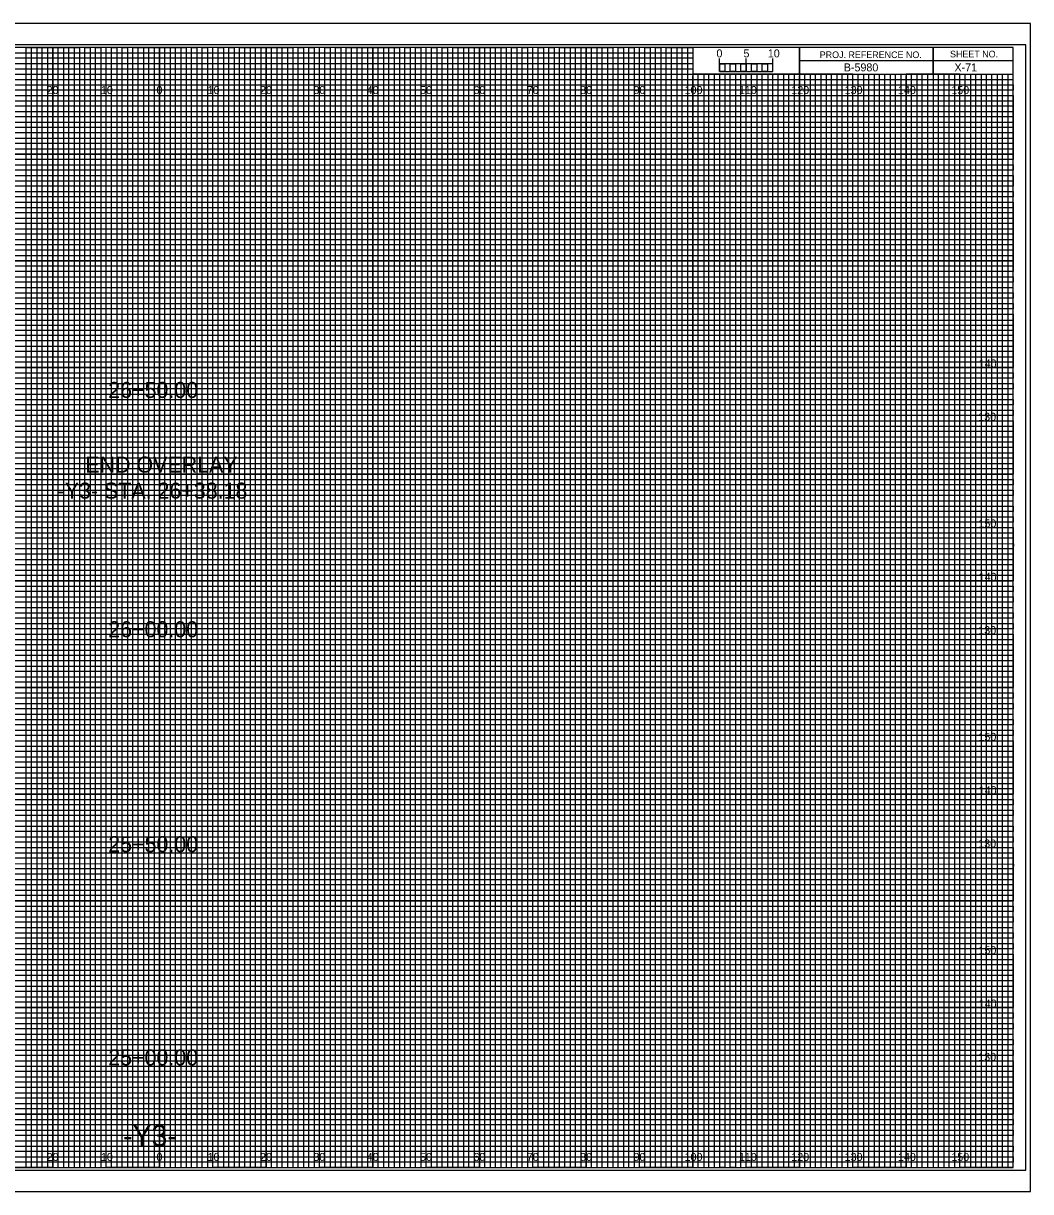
# Model space of a CAD drawing. Extents: x -13 to 323, y -5 to 434.
# Drawn here: x 134.5 to 323.3, y 215.5 to 434.5 of the extents above; entities that cross this region are included whole.
import ezdxf

# ---------------------------------------------------------------- set-up
doc = ezdxf.new("R2010")
doc.units = 0
for name, color, linetype in [('Exist Cross Section Cell', 7, 'Continuous'), ('Exist XS Center Line Elevation Label', 7, 'Continuous'), ('Exist XS Ground Line', 7, 'Continuous'), ('Prop CMT Pvmt Course 1', 7, 'Continuous'), ('Prop CMT Pvmt Course 2', 7, 'Continuous'), ('Prop CMT Pvmt Course 3', 7, 'Continuous'), ('Prop CMT Pvmt Surface', 7, 'Continuous'), ('Prop CMT Pvmt Surface Shoulder', 7, 'Continuous'), ('Prop CMT Shld Paved Course 1', 7, 'Continuous'), ('Prop CMT Shld Paved Course 2', 7, 'Continuous'), ('Prop CMT Shld Paved Course 3', 7, 'Continuous'), ('Prop CMT Slope Grass', 7, 'Continuous'), ('Prop CMT Subgrade Earthwork', 7, 'Continuous'), ('Prop SS Cut Text', 7, 'Continuous'), ('Prop SS Fill Line', 7, 'Continuous'), ('Prop SS Transition Line', 7, 'Continuous'), ('Prop XS Side Slope Text', 7, 'Continuous')]:
    doc.layers.add(name, color=color, linetype=linetype)

msp = doc.modelspace()

# ---------------------------------------------------------------- linework, layer by layer
at = {"layer": 'Exist XS Center Line Elevation Label'}
for points in [[(125, 220), (135, 220), (135, 430), (145, 430), (145, 220), (155, 220), (155, 430), (165, 430), (165, 220), (175, 220), (175, 430), (185, 430), (185, 220), (195, 220), (195, 430), (205, 430), (205, 220), (215, 220), (215, 430), (225, 430), (225, 220), (235, 220), (235, 430), (245, 430), (245, 220), (255, 220), (255, 430), (259.93, 430), (260, 430), (260, 425), (264.99, 425), (264.99, 220), (275, 220), (275, 425), (285, 425), (285, 220), (295, 220), (295, 425), (305, 425), (305, 220), (315, 220), (315, 425)], [(0, 425), (275, 425)], [(0, 405), (320, 405), (320, 415), (0, 415)], [(0, 385), (320, 385), (320, 395), (0, 395)], [(0, 365), (320, 365), (320, 375), (0, 375)], [(0, 345), (320, 345), (320, 355), (0, 355)], [(0, 325), (320, 325), (320, 335), (0, 335)], [(0, 305), (320, 305), (320, 315), (0, 315)], [(0, 285), (320, 285), (320, 295), (0, 295)], [(0, 265), (320, 265), (320, 275), (0, 275)], [(0, 245), (320, 245), (320, 255), (0, 255)], [(0, 225), (320, 225), (320, 235), (0, 235)]]:
    msp.add_lwpolyline(points, dxfattribs=at)
at = {"layer": 'Exist XS Ground Line'}
for p, q in [((150, 430), (140, 430)), ((140, 430), (140, 220)), ((150, 220), (150, 430)), ((170, 430), (160, 430)), ((160, 430), (160, 220)), ((170, 220), (170, 430)), ((190, 430), (180, 430)), ((180, 430), (180, 220)), ((190, 220), (190, 430)), ((210, 430), (200, 430)), ((200, 430), (200, 220)), ((210, 220), (210, 430)), ((230, 430), (220, 430)), ((220, 430), (220, 220)), ((230, 220), (230, 430)), ((250, 430), (240, 430)), ((240, 430), (240, 220)), ((250, 220), (250, 430)), ((260, 430), (260, 220)), ((270, 220), (270, 425)), ((290, 425), (280, 425)), ((280, 425), (280, 220)), ((290, 220), (290, 425)), ((310, 425), (300, 425)), ((300, 425), (300, 220)), ((310, 220), (310, 425)), ((140, 220), (130, 220)), ((160, 220), (150, 220)), ((180, 220), (170, 220)), ((200, 220), (190, 220)), ((220, 220), (210, 220)), ((240, 220), (230, 220)), ((260, 220), (250, 220)), ((280, 220), (270, 220)), ((300, 220), (290, 220)), ((320, 220), (310, 220)), ((320, 220), (320, 220))]:
    msp.add_line(p, q, dxfattribs=at)
for points in [[(0, 420), (320, 420), (320, 410), (0, 410)], [(0, 400), (320, 400), (320, 390), (0, 390)], [(0, 380), (320, 380), (320, 370), (0, 370)], [(0, 360), (320, 360), (320, 350), (0, 350)], [(0, 340), (320, 340), (320, 330), (0, 330)], [(0, 320), (320, 320), (320, 310), (0, 310)], [(0, 300), (320, 300), (320, 290), (0, 290)], [(0, 280), (320, 280), (320, 270), (0, 270)], [(0, 260), (320, 260), (320, 250), (0, 250)], [(0, 240), (320, 240), (320, 230), (0, 230)]]:
    msp.add_lwpolyline(points, dxfattribs=at)
at = {"layer": 'Prop CMT Pvmt Course 1'}
for p, q in [((265, 425.49), (265, 427.9)), ((265, 426.9), (265, 427.9)), ((270, 425.49), (270, 427.9)), ((275, 425.49), (275, 427.9)), ((275, 426.9), (275, 427.9))]:
    msp.add_line(p, q, dxfattribs=at)
for points in [[(275, 426.9), (265, 426.9), (265, 425.49), (275, 425.49)], [(265, 426.9), (266, 426.9), (266, 425.49), (265, 425.49)], [(267, 426.9), (268, 426.9), (268, 425.49), (267, 425.49)], [(269, 426.9), (270, 426.9), (270, 425.49), (269, 425.49)], [(271, 426.9), (272, 426.9), (272, 425.49), (271, 425.49)], [(273, 426.9), (274, 426.9), (274, 425.49), (273, 425.49)]]:
    msp.add_lwpolyline(points, close=True, dxfattribs=at)
at = {"layer": 'Prop CMT Pvmt Course 2'}
for p, q in [((0, 429), (260, 429)), ((260, 427.98), (0, 427.98)), ((260, 429), (260, 427.98)), ((0, 427), (260, 427)), ((260, 425.89), (0, 425.89)), ((260, 427), (260, 425.89)), ((0, 424), (320, 424))]:
    msp.add_line(p, q, dxfattribs=at)
for points in [[(0, 423), (270, 423), (320, 423), (320, 422), (0, 422)], [(0, 421), (320, 421), (320, 419), (0, 419)], [(0, 418), (320, 418), (320, 417), (0, 416.98)], [(0, 416), (320, 416), (320, 414), (0, 414)], [(0, 413), (320, 413), (320, 412), (0, 412)], [(0, 411), (320, 411), (320, 409), (0, 409)], [(0, 408), (320, 408), (320, 407), (0, 407)], [(0, 406), (320, 406), (320, 404), (0, 404)], [(0, 403), (320, 403), (320, 402), (0, 402)], [(0, 401), (320, 401), (320, 399), (0, 399)], [(0, 398), (320, 398), (320, 397), (0, 397)], [(0, 396), (320, 396), (320, 393.95), (320, 393), (320, 392), (0, 392)], [(0, 394), (320, 394), (320, 393), (0, 393)], [(0, 391), (320, 391), (320, 389), (0, 389.03)], [(0, 389.03), (320, 389), (320, 388), (0, 388)], [(0, 387), (320, 387), (320, 386), (0, 386)], [(0, 384), (320, 384), (320, 383), (0, 383)], [(0, 382), (320, 382), (320, 381), (0, 381)], [(-0.07, 378.89), (320, 378.89), (320, 377.88), (-0.07, 377.88)], [(0, 377), (320, 377), (320, 376), (0, 376)], [(0, 374), (320, 374), (320, 373), (0, 373)], [(0, 372), (320, 372), (320, 371), (0, 371)], [(0, 369), (320, 369), (320, 368), (0, 368)], [(0, 367), (320, 367), (320, 366), (0, 366)], [(0, 364), (320, 364), (320, 363), (0, 363)], [(0, 362), (320, 362), (320, 361), (0, 361)], [(0, 359), (320, 359), (319.99, 357.98), (0, 358)], [(0, 357), (320, 357), (320, 356), (0, 356)], [(0, 354), (320, 354), (320, 353), (0, 353)], [(0, 352), (320, 352), (320, 351), (0, 351)], [(0, 349), (320, 349), (320, 348), (0, 348)], [(0, 347), (320, 347), (320, 346), (0, 346)], [(0, 344), (320, 344), (320, 343), (0, 343)], [(0, 342), (320, 342), (320, 341), (0, 341)], [(0, 339), (320, 339), (320, 338), (0, 338)], [(0, 336.99), (320.07, 336.91), (320, 336), (0, 336)], [(0, 334), (320, 334), (320, 333), (0, 333)], [(0, 332), (320, 332), (320, 331), (0, 331)], [(0, 329), (320, 329), (320, 328), (0, 328)], [(0, 327), (320, 327), (320, 326), (0, 326)], [(0, 324), (320, 324), (320, 323), (0, 323)], [(0, 322), (320, 322), (320, 321), (0, 321)], [(0, 319), (320, 319), (320, 318), (0, 318)], [(0, 317), (320, 317), (320, 316), (0, 316)], [(0, 314), (320, 314), (320, 313), (0, 313)], [(0, 312), (320, 312), (320, 311), (0, 311)], [(0, 309), (320, 309), (320, 308), (0, 308)], [(0, 307), (320, 307), (320, 306), (0, 306)], [(0, 304), (320, 304), (320, 303), (0, 303)], [(0, 302), (320, 302), (320, 301), (0, 301)], [(0, 299), (320, 299), (319.99, 297.98), (0, 298)], [(0, 297), (320, 297), (320, 296), (0, 296)], [(0, 294), (320, 294), (320, 293), (0, 293)], [(0, 292), (320, 292), (320, 291), (0, 291)], [(0, 289), (320, 289), (320, 288), (0, 288)], [(0, 287), (320, 287), (320, 286), (0, 286)], [(0, 284), (320, 284), (320, 283), (0, 283)], [(0, 282), (320, 282), (320, 281), (0, 281)], [(0, 279), (320, 279), (320, 278), (0, 278)], [(0, 276.99), (320.07, 276.91), (320, 276), (0, 276)], [(0, 274), (320, 274), (320, 273), (0, 273)], [(0, 272), (320, 272), (320, 271), (0, 271)], [(0, 269), (320, 269), (320, 268), (0, 268)], [(0, 267), (320, 267), (320, 266), (0, 266)], [(0, 264), (320, 264), (320, 263), (0, 263)], [(0, 262), (320, 262), (320, 261), (0, 261)], [(0, 259), (320, 259), (320, 258), (0, 258)], [(0, 257), (320, 257), (320, 256), (0, 256)], [(0, 254), (320, 254), (320, 253), (0, 253)], [(0, 252), (320, 252), (320, 251), (0, 251)], [(0, 249), (320, 249), (320, 248), (0, 248)], [(0, 247), (320, 247), (320, 246), (0, 246)], [(0, 244), (320, 244), (320, 243), (0, 243)], [(0, 242), (320, 242), (320, 241), (0, 241)], [(0, 239), (320, 239), (320, 238), (0, 238)], [(0, 237), (320, 237), (320, 236), (0, 236)], [(0, 234), (320, 234), (320, 233), (0, 233)], [(0, 232), (320, 232), (320, 231), (0, 231)], [(0, 229), (320, 229), (320, 228), (0, 228)], [(0, 227), (320, 227), (320, 226), (0, 226)], [(0, 224), (320, 224), (320, 223), (0, 223)], [(0, 222), (320, 222), (320, 221), (0, 221)]]:
    msp.add_lwpolyline(points, dxfattribs=at)
at = {"layer": 'Prop CMT Pvmt Course 3'}
for p, q in [((305, 430), (305, 425)), ((305, 425), (305, 430)), ((280, 427.5), (280, 425)), ((320, 427.49), (280, 427.49)), ((280, 425), (320, 425))]:
    msp.add_line(p, q, dxfattribs=at)
for points in [[(320, 430), (0, 430), (0, 220), (320, 220)], [(280, 430), (260, 430), (260, 425.03), (280, 425.03)], [(320, 430), (280, 430), (280, 425), (320, 425)]]:
    msp.add_lwpolyline(points, close=True, dxfattribs=at)
at = {"layer": 'Prop CMT Pvmt Surface'}
for p, q in [((267, 425), (266.01, 425)), ((266.01, 425), (266.01, 220)), ((267, 220), (267, 425)), ((269, 425), (268, 425)), ((268, 425), (268, 220)), ((269, 220), (269, 425)), ((266.01, 220), (265, 220)), ((268, 220), (267, 220))]:
    msp.add_line(p, q, dxfattribs=at)
for points in [[(135, 220), (136, 220), (136, 430), (137, 430), (137, 220)], [(137, 220), (138, 220), (138, 430), (139, 430), (139, 220)], [(140, 220), (141, 220), (141, 430), (142, 430), (142, 220)], [(142, 220), (143, 220), (143, 430), (144, 430), (144, 220)], [(145, 220), (146, 220), (146, 430), (147, 430), (147, 220)], [(147, 220), (148, 220), (148, 430), (149, 430), (149, 220)], [(150, 220), (151, 220), (151, 430), (152, 430), (152, 220)], [(152, 220), (153, 220), (153, 430), (154, 430), (154, 220)], [(155, 220), (156, 220), (156, 430), (157, 430), (157, 220)], [(157, 220), (158, 220), (158, 430), (159, 430), (159, 220)], [(160, 220), (161, 220), (161, 430), (162, 430), (162, 220)], [(162, 220), (163, 220), (163, 430), (164, 430), (164, 220)], [(165, 220), (166, 220), (166, 430), (167, 430), (167, 220)], [(167, 220), (168, 220), (168, 430), (169, 430), (169, 220)], [(170, 220), (171, 220), (171, 430), (172, 430), (172, 220)], [(172, 220), (173, 220), (173, 430), (174, 430), (174, 220)], [(175, 220), (176, 220), (176, 430), (177, 430), (177, 220)], [(177, 220), (178, 220), (178, 430), (179, 430), (179, 220)], [(180, 220), (181, 220), (181, 430), (182, 430), (182, 220)], [(182, 220), (183, 220), (183, 430), (184, 430), (184, 220)], [(185, 220), (186, 220), (186, 430), (187, 430), (187, 220)], [(187, 220), (188, 220), (188, 430), (189, 430), (189, 220)], [(190, 220), (191, 220), (191, 430), (192, 430), (192, 220)], [(192, 220), (193, 220), (193, 430), (194, 430), (194, 220)], [(195, 220), (196, 220), (196, 430), (197, 430), (197, 220)], [(197, 220), (198, 220), (198, 430), (199, 430), (199, 220)], [(200, 220), (201, 220), (201, 430), (202, 430), (202, 220)], [(202, 220), (203, 220), (203, 430), (204, 430), (204, 220)], [(205, 220), (206, 220), (206, 430), (207, 430), (207, 220)], [(207, 220), (208, 220), (208, 430), (209, 430), (209, 220)], [(210, 220), (211, 220), (211, 430), (212, 430), (212, 220)], [(212, 220), (213, 220), (213, 430), (214, 430), (214, 220)], [(215, 220), (216, 220), (216, 430), (217, 430), (217, 220)], [(217, 220), (218, 220), (218, 430), (219, 430), (219, 220)], [(220, 220), (221, 220), (221, 430), (222, 430), (222, 220)], [(222, 220), (223, 220), (223, 430), (224, 430), (224, 220)], [(225, 220), (226, 220), (226, 430), (227, 430), (227, 220)], [(227, 220), (228, 220), (228, 430), (229, 430), (229, 220)], [(230, 220), (231, 220), (231, 430), (232, 430), (232, 220)], [(232, 220), (233, 220), (233, 430), (234, 430), (234, 220)], [(235, 220), (236, 220), (236, 430), (237, 430), (237, 220)], [(237, 220), (238, 220), (238, 430), (239, 430), (239, 220)], [(240, 220), (241, 220), (241, 430), (242, 430), (242, 220)], [(242, 220), (243, 220), (243, 430), (244, 430), (244, 220)], [(245, 220), (246, 220), (246, 430), (247, 430), (247, 220)], [(247, 220), (248, 220), (248, 430), (249, 430), (249, 220)], [(250, 220), (251, 220), (251, 430), (252, 430), (252, 220)], [(252, 220), (253, 220), (253, 430), (254, 430), (254, 220)], [(255, 220), (256, 220), (256, 430), (257, 430), (257, 220)], [(257, 220), (258, 220), (258, 430), (259, 430), (259, 220)], [(260, 220), (261, 220), (261, 425), (262.02, 425), (262.02, 220)], [(262, 220), (263, 220), (263, 425), (263.99, 425), (263.99, 220)], [(270, 220), (270.98, 220), (270.98, 425), (272, 425), (272, 220)], [(272, 220), (273, 220), (273, 425), (274.05, 425), (274.05, 220)], [(275, 220), (276, 220), (276, 425), (277, 425), (277, 220)], [(277, 220), (278, 220), (278, 425), (279, 425), (279, 220)], [(280, 220), (281, 220), (281, 425), (282, 425), (282, 220)], [(282, 220), (283, 220), (283, 425), (284, 425), (284, 220)], [(285, 220), (286, 220), (286, 425), (287, 425), (287, 220)], [(287, 220), (288, 220), (288, 425), (289, 425), (289, 220)], [(290, 220), (291, 220), (291, 425), (292, 425), (292, 220)], [(292, 220), (293, 220), (293, 425), (294, 425), (294, 220)], [(295, 220), (296, 220), (296, 425), (297, 425), (297, 220)], [(297, 220), (298, 220), (298, 425), (299, 425), (299, 220)], [(300, 220), (301, 220), (301, 425), (302, 425), (302, 220)], [(302, 220), (303, 220), (303, 425), (304, 425), (304, 220)], [(305, 220), (306, 220), (306, 425), (307, 425), (307, 220)], [(307, 220), (308, 220), (308, 425), (309, 425), (309, 220)], [(310, 220), (311, 220), (311, 425), (312, 425), (312, 220)], [(312, 220), (313, 220), (313, 425), (314, 425), (314, 220)], [(315, 220), (316, 220), (316, 425), (317, 425), (317, 220)], [(317, 220), (318, 220), (318, 425), (319, 425), (319, 220)]]:
    msp.add_lwpolyline(points, dxfattribs=at)
at = {"layer": 'Prop CMT Pvmt Surface Shoulder'}
msp.add_lwpolyline([(-10.8, 219.5), (322.4, 219.5), (322.4, 430.5), (-10.8, 430.5)], close=True, dxfattribs=at)
at = {"layer": 'Prop CMT Shld Paved Course 1'}
for p, q in [((140, 220), (140, 430)), ((150, 220), (150, 430)), ((160, 220), (160, 430)), ((170, 220), (170, 430)), ((180, 220), (180, 430)), ((190, 220), (190, 430)), ((200, 220), (200, 430)), ((210, 220), (210, 430)), ((220, 220), (220, 430)), ((230, 220), (230, 430)), ((240, 220), (240, 430)), ((250, 220), (250, 430)), ((260, 220), (260, 424.69)), ((270, 220), (270, 424.69)), ((280, 220), (280, 424.69)), ((290, 220), (290, 424.69)), ((300, 220), (300, 424.69)), ((310, 220), (310, 424.69)), ((0, 420), (320, 420)), ((0, 410), (320, 410)), ((0, 400), (320, 400)), ((0, 390), (320, 390)), ((0, 380), (320, 380)), ((0, 370), (320, 370)), ((0, 360), (320, 360)), ((0, 350), (320, 350)), ((0, 340), (320, 340)), ((0, 330), (320, 330)), ((0, 320), (320, 320)), ((0, 310), (320, 310)), ((0, 300), (320, 300)), ((0, 290), (320, 290)), ((0, 280), (320, 280)), ((0, 270), (320, 270)), ((0, 260), (320, 260)), ((0, 250), (320, 250)), ((0, 240), (320, 240)), ((0, 230), (320, 230))]:
    msp.add_line(p, q, dxfattribs=at)
at = {"layer": 'Prop CMT Shld Paved Course 2'}
for p, q in [((323.3, 434.5), (-13.4, 434.5)), ((-13.4, 215.5), (323.3, 215.5))]:
    msp.add_line(p, q, dxfattribs=at)
at = {"layer": 'Prop CMT Subgrade Earthwork'}
msp.add_lwpolyline([(-13.4, 215.5), (323.3, 215.5), (323.3, 434.5), (-13.4, 434.5)], close=True, dxfattribs=at)

# ---------------------------------------------------------------- texts
at = {"layer": 'Exist Cross Section Cell'}
for s, p in [('20', (138.86, 421.25)), ('10', (149.04, 421.25)), ('0', (159.45, 421.25)), ('0', (159.45, 421.25)), ('10', (169.04, 421.25)), ('20', (178.86, 421.25)), ('30', (188.86, 421.25)), ('40', (198.86, 421.25)), ('50', (208.86, 421.25)), ('60', (218.86, 421.25)), ('70', (228.86, 421.25)), ('80', (238.86, 421.25)), ('90', (248.86, 421.25)), ('100', (258.44, 421.25)), ('110', (268.62, 421.25)), ('120', (278.44, 421.25)), ('130', (288.44, 421.25)), ('140', (298.44, 421.25)), ('150', (308.44, 421.25)), ('20', (138.86, 221.25)), ('10', (149.04, 221.25)), ('0', (159.45, 221.25)), ('0', (159.45, 221.25)), ('10', (169.04, 221.25)), ('20', (178.86, 221.25)), ('30', (188.86, 221.25)), ('40', (198.86, 221.25)), ('50', (208.86, 221.25)), ('60', (218.86, 221.25)), ('70', (228.86, 221.25)), ('80', (238.86, 221.25)), ('90', (248.86, 221.25)), ('100', (258.44, 221.25)), ('110', (268.62, 221.25)), ('120', (278.44, 221.25)), ('130', (288.44, 221.25)), ('140', (298.44, 221.25)), ('150', (308.44, 221.25))]:
    msp.add_text(s, height=1.5, dxfattribs=at).set_placement(p)
at = {"layer": 'Prop CMT Pvmt Course 1'}
msp.add_text('0', height=1.5, dxfattribs=at).set_placement((264.41, 428.12))
at = {"layer": 'Prop CMT Pvmt Course 3'}
for s, p in [('PROJ. REFERENCE NO.', (283.77, 427.99)), ('SHEET NO.', (308.19, 428.12))]:
    msp.add_text(s, height=1.25, dxfattribs=at).set_placement(p)
at = {"layer": 'Prop CMT Shld Paved Course 3'}
for s, p in [('140', (313.57, 370)), ('130', (313.49, 360)), ('150', (313.52, 340)), ('140', (313.57, 330)), ('130', (313.49, 320)), ('150', (313.52, 300)), ('140', (313.57, 290)), ('130', (313.49, 280)), ('150', (313.52, 260)), ('140', (313.57, 250)), ('130', (313.49, 240))]:
    msp.add_text(s, height=1.5, dxfattribs=at).set_placement(p)
at = {"layer": 'Prop CMT Slope Grass'}
for s, p in [('26+50.00', (150.41, 364.28)), ('END OVERLAY', (146.12, 350.29)), ('-Y3- STA. 26+38.18', (140.92, 345.41)), ('26+00.00', (150.41, 319.42)), ('25+50.00', (150.41, 279.13)), ('25+00.00', (150.41, 239.16))]:
    msp.add_text(s, height=3, dxfattribs=at).set_placement(p)
at = {"layer": 'Prop SS Cut Text'}
msp.add_text('-Y3-', height=4, dxfattribs=at).set_placement((153.17, 224))
at = {"layer": 'Prop SS Fill Line'}
for s, p in [('5', (269.47, 428.12)), ('10', (274.04, 428.12))]:
    msp.add_text(s, height=1.5, dxfattribs=at).set_placement(p)
at = {"layer": 'Prop SS Transition Line'}
msp.add_text('B-5980', height=1.5, dxfattribs=at).set_placement((288.28, 425.5))
at = {"layer": 'Prop XS Side Slope Text'}
msp.add_text('X-71', height=1.5, dxfattribs=at).set_placement((309.02, 425.5))

doc.saveas('drawing.dxf')
